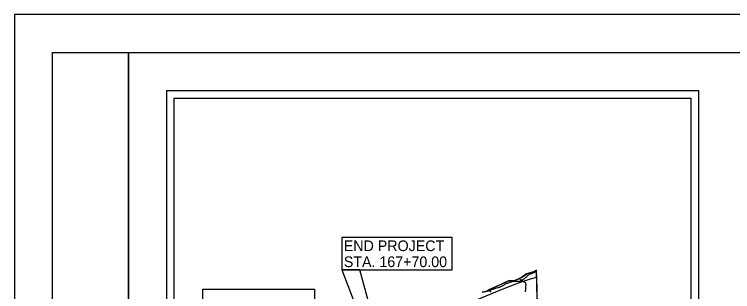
# Model space of a CAD drawing. Extents: x -5.4 to 71.3, y -12 to 22.
# Drawn here: x 0 to 9.45, y 18.36 to 22 of the extents above; entities that cross this region are included whole.
import ezdxf

# ---------------------------------------------------------------- set-up
doc = ezdxf.new("R2010")
doc.units = 0
for name, color, linetype in [('GM_X_City_Street', 7, 'Continuous'), ('GM_X_Major_Lake', 7, 'Continuous'), ('GM_X_Minor_River', 7, 'Continuous'), ('GM_X_Minor_River_Text', 7, 'Continuous'), ('PM_X_Surveyed_Line', 7, 'Continuous'), ('SH_Border', 7, 'Continuous'), ('SH_Cut_Line', 7, 'Continuous'), ('SH_Data', 7, 'Continuous'), ('SH_Text', 7, 'Continuous')]:
    doc.layers.add(name, color=color, linetype=linetype)

msp = doc.modelspace()

# ---------------------------------------------------------------- linework, layer by layer
at = {"layer": 'GM_X_City_Street'}
msp.add_lwpolyline([(5.7326, 18.1109), (6.1537, 18.2812), (6.3856, 18.3767), (6.6338, 18.4748), (6.7914, 18.529), (6.8726, 18.5488)], dxfattribs=at)
at = {"layer": 'GM_X_Major_Lake'}
for points in [[(6.8166, 18.6157), (6.8321, 18.6199), (6.8714, 18.6385)], [(6.1552, 18.3521), (6.2038, 18.3619), (6.2532, 18.3865), (6.3626, 18.4332), (6.4367, 18.4704), (6.5123, 18.506), (6.5777, 18.501), (6.6745, 18.5451), (6.7414, 18.5906), (6.8166, 18.6157)]]:
    msp.add_lwpolyline(points, dxfattribs=at)
at = {"layer": 'GM_X_Minor_River'}
for points in [[(6.6433, 18.5309), (6.6462, 18.5274), (6.6552, 18.5177), (6.6655, 18.5122), (6.6748, 18.5055), (6.6852, 18.4985), (6.6959, 18.493), (6.7063, 18.4879), (6.7147, 18.4827), (6.7232, 18.4741), (6.7272, 18.4647), (6.7282, 18.453), (6.7276, 18.4431), (6.7266, 18.4335), (6.7257, 18.4236), (6.7262, 18.4119), (6.7272, 18.4005), (6.7267, 18.3891), (6.7245, 18.3792), (6.7206, 18.3654), (6.7189, 18.3559)], [(6.2544, 18.387), (6.2543, 18.377), (6.2576, 18.3668), (6.2657, 18.3601), (6.273, 18.3511)]]:
    msp.add_lwpolyline(points, dxfattribs=at)
at = {"layer": 'GM_X_Minor_River_Text'}
msp.add_lwpolyline([(6.9247, 16.3154), (6.8724, 18.5494), (6.8707, 18.6188), (6.8455, 18.6087), (6.8335, 18.6041), (6.8194, 18.5993), (6.803, 18.594), (6.7928, 18.5911), (6.7888, 18.5911), (6.7842, 18.5911), (6.7801, 18.5891), (6.7767, 18.5853), (6.7694, 18.5799), (6.7632, 18.5758), (6.7571, 18.5702), (6.7517, 18.5653), (6.7448, 18.5556), (6.7384, 18.5491), (6.727, 18.5408), (6.7168, 18.5342), (6.7027, 18.5223), (6.6941, 18.5164), (6.6777, 18.5062), (6.6639, 18.499), (6.652, 18.4931), (6.6435, 18.4898), (6.6369, 18.4885), (6.6267, 18.4898), (6.6155, 18.4905), (6.6073, 18.4898), (6.5942, 18.4918), (6.586, 18.4918), (6.5748, 18.4928), (6.5636, 18.4901), (6.5534, 18.4868), (6.5396, 18.4845), (6.5153, 18.4816), (6.5093, 18.477), (6.5011, 18.4717), (6.4919, 18.4678), (6.4827, 18.4668), (6.4745, 18.4648), (6.462, 18.4586), (6.4498, 18.4503), (6.4367, 18.4411), (6.4261, 18.4355), (6.415, 18.4309), (6.4064, 18.4273), (6.3956, 18.4211), (6.3847, 18.4138), (6.3749, 18.4119), (6.3653, 18.4105), (6.341, 18.4023), (6.3229, 18.3958), (6.3045, 18.3895), (6.295, 18.3875), (6.2874, 18.3849), (6.2733, 18.3823), (6.2598, 18.375), (6.2456, 18.3685), (6.2213, 18.3586)], dxfattribs=at)
at = {"layer": 'PM_X_Surveyed_Line'}
msp.add_lwpolyline([(6.9275, 16.1897), (6.8702, 18.6385), (6.8309, 18.6199), (6.8155, 18.6157), (6.7403, 18.5906), (6.6734, 18.5451), (6.5765, 18.5011), (6.5112, 18.506), (6.4356, 18.4704), (6.3615, 18.4332), (6.2521, 18.3866), (6.2027, 18.3619), (6.154, 18.3521)], dxfattribs=at)
at = {"layer": 'SH_Border'}
for points in [[(0.5, 21.5), (1.5, 21.5), (1.5, 0.5), (0.5, 0.5)], [(1.5, 21.5), (33.5, 21.5), (33.5, 0.5), (1.5, 0.5)], [(4.3095, 18.6434), (5.7614, 18.6434), (5.7614, 19.0717), (4.3095, 19.0717)], [(2.4787, 18.3897), (3.9503, 18.3897), (3.9503, 17.9593), (2.4787, 17.9593)]]:
    msp.add_lwpolyline(points, close=True, dxfattribs=at)
at = {"layer": 'SH_Cut_Line'}
msp.add_lwpolyline([(0, 0), (34, 0), (34, 22), (0, 22)], close=True, dxfattribs=at)
msp.add_lwpolyline([(6.9247, 16.3154), (6.8724, 18.5494), (6.8707, 18.6188), (6.8455, 18.6087), (6.8335, 18.6041), (6.8194, 18.5993), (6.803, 18.594), (6.7928, 18.5911), (6.7888, 18.5911), (6.7842, 18.5911), (6.7801, 18.5891), (6.7767, 18.5853), (6.7694, 18.5799), (6.7632, 18.5758), (6.7571, 18.5702), (6.7517, 18.5653), (6.7448, 18.5556), (6.7384, 18.5491), (6.727, 18.5408), (6.7168, 18.5342), (6.7027, 18.5223), (6.6941, 18.5164), (6.6777, 18.5062), (6.6639, 18.499), (6.652, 18.4931), (6.6435, 18.4898), (6.6369, 18.4885), (6.6267, 18.4898), (6.6155, 18.4905), (6.6073, 18.4898), (6.5942, 18.4918), (6.586, 18.4918), (6.5748, 18.4928), (6.5636, 18.4901), (6.5534, 18.4868), (6.5396, 18.4845), (6.5153, 18.4816), (6.5093, 18.477), (6.5011, 18.4717), (6.4919, 18.4678), (6.4827, 18.4668), (6.4745, 18.4648), (6.462, 18.4586), (6.4498, 18.4503), (6.4367, 18.4411), (6.4261, 18.4355), (6.415, 18.4309), (6.4064, 18.4273), (6.3956, 18.4211), (6.3847, 18.4138), (6.3749, 18.4119), (6.3653, 18.4105), (6.341, 18.4023), (6.3229, 18.3958), (6.3045, 18.3895), (6.295, 18.3875), (6.2874, 18.3849), (6.2733, 18.3823), (6.2598, 18.375), (6.2456, 18.3685), (6.2213, 18.3586)], dxfattribs=at)
at = {"layer": 'SH_Data'}
for p, q in [((2, 21), (9, 21)), ((2, 21), (2, 14)), ((9, 21), (9, 14)), ((2.1, 20.9), (2.1, 14.1)), ((2.1, 20.9), (8.9, 20.9)), ((8.9, 20.9), (8.9, 14.1))]:
    msp.add_line(p, q, dxfattribs=at)
at = {"layer": 'SH_Text'}
msp.add_lwpolyline([(4.3095, 18.6434), (5.1284, 16.5056), (4.5432, 18.6434)], close=True, dxfattribs=at)

# ---------------------------------------------------------------- texts
for s, p in [('END PROJECT', (4.3349, 18.8909)), ('STA. 167+70.00  ', (4.3349, 18.6809))]:
    msp.add_text(s, height=0.14, dxfattribs=at).set_placement(p)

doc.saveas('drawing.dxf')
